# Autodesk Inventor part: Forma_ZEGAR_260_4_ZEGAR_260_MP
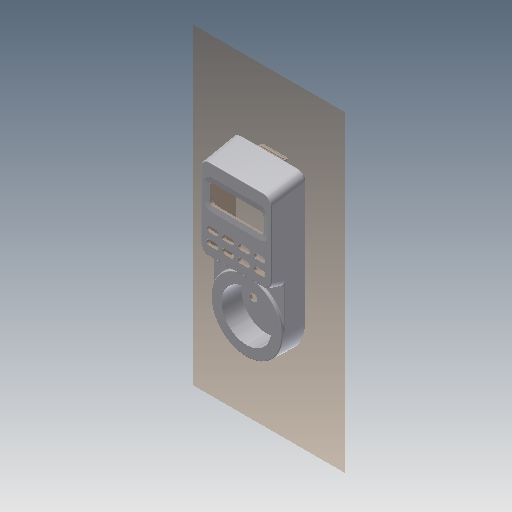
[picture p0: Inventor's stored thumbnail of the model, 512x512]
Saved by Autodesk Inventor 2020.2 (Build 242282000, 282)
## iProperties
Created: 2015-01
Part Number: Forma_ZEGAR_260_4_ZEGAR_260_MP
Material: Ogólny
Document SubType Name: Modeling
Designer: F.Stasiak
Density: 1 g/cm^3
Appearance: Domyślna
Catalog Web Link: www.expertbooks.pl
Manager: www.cadconsulting.pl
Company: Fabian Stasiak CAD Consulting
Author: F.Stasiak
Subject: Zbiór ćwiczeń. Autodesk Inventor 2020. Kurs Professional
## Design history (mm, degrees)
derived "ZEGAR_260.ipt"
node "Forma_ZEGAR_260_4_ZEGAR_260_WP"
feature "Zamknij obwiednię1" dims "d7" = 5, "d8" = 5, "d9" = 5, "d10" = 5, "d11" = 0
feature "Zamknij obwiednię2" dims "d12" = 5, "d13" = 5, "d14" = 5, "d15" = 5, "d16" = 0
feature "Zamknij obwiednię3" dims "d17" = 5, "d18" = 5, "d19" = 5, "d20" = 5, "d21" = 5, "d22" = 5, "d23" = 5, "d24" = 5, "d25" = 0
feature "Zamknij obwiednię4" dims "d26" = 5, "d27" = 5, "d28" = 5, "d29" = 5, "d30" = 0
feature "Zamknij obwiednię5" dims "d31" = 5, "d32" = 5, "d33" = 5, "d34" = 5, "d35" = 0
feature "Zamknij obwiednię6" dims "d36" = 5, "d37" = 5, "d38" = 5, "d39" = 5, "d40" = 0
feature "Zamknij obwiednię7" dims "d41" = 5, "d42" = 5, "d43" = 5, "d44" = 5, "d45" = 0
feature "Zamknij obwiednię8" dims "d46" = 5, "d47" = 5, "d48" = 5, "d49" = 5, "d50" = 0
feature "Zamknij obwiednię9" dims "d51" = 5, "d52" = 5, "d53" = 5, "d54" = 5, "d55" = 0
feature "Zamknij obwiednię10" dims "d56" = 5, "d57" = 0
feature "Zamknij obwiednię11" dims "d58" = 5, "d59" = 0
feature "Zamknij obwiednię12" dims "d60" = 5, "d61" = 0
node "Płaszczyzna konstrukcyjna1"
sketch "Szkic1"
  geometry: L1 (30.835, -178.031)-(30.835, 61.969); L2 (30.835, 61.969)-(-86.165, 61.969); L3 (-86.165, 61.969)-(-86.165, -178.031); L4 (-86.165, -178.031)-(30.835, -178.031); L5 (0, 0)-(0, -94.499) reference; L6 (-55.33, -94.499)-(-55.33, 0) reference; L7 (-49.319, 6.101)-(-6.011, 6.101) reference; A1 r 27.665 centre (-27.665, -94.499) between (-55.33, -94.499) and (0, -94.499) reference; 3 further points; 2 other entities
  constraints: 8 end point, 2 other
  dimensions: "d62" = 58.5 horizontal distance of point (-27.665, -58.031) L1.end (= 1.5 x Xmax); "d63" = 120 vertical distance of point (-27.665, -58.031) L1.end (= 1.5 x Ymax); "d64" = 58.5 horizontal distance of point (-27.665, -58.031) L2.end (= -1.5 x Xmin); "d65" = 120 vertical distance of point (-27.665, -58.031) L2.end (= 1.5 x Ymax); "d66" = 58.5 horizontal distance of point (-27.665, -58.031) L3.end (= -1.5 x Xmin); "d67" = 120 vertical distance of point (-27.665, -58.031) L3.end (= -1.5 x Ymin); "d68" = 58.5 horizontal distance of point (-27.665, -58.031) L1.start (= 1.5 x Xmax); "d69" = 120 vertical distance of point (-27.665, -58.031) L1.start (= -1.5 x Ymin)
feature "Zamknij obwiednię13" sketch "Szkic1"
feature "Oddzielenie matrycy1"
node "Płaszczyzna konstrukcyjna2"
sketch "Szkic2"
  geometry: L1 (0, -78)-(-20.191, -78) reference; L2 (-20.191, -78)-(-20.191, 0) reference; L3 (-17.791, -39)-(-12.991, -39); L4 (-17.791, -39)-(-15.391, -39); L5 (-17.791, -39)-(-17.791, -29.75); L6 (-20.191, -48.25)-(-15.391, -48.25); L7 (-15.391, -48.25)-(-15.391, -29.75); L8 (-15.391, -29.75)-(-20.191, -29.75); L9 (-20.191, -29.75)-(-20.191, -48.25)
  constraints: 14 end point, 1 horizontal, 1 perpendicular, 2 other
  dimensions: "d71" = 39 distance from line of L1 L3.start; "d72" = 2.4 distance from line of L2 L3.start; "d73" = 0 distance between parallel lines of L3 L4; "d74" = 4.8 distance between parallel lines of L9 L7; "d75" = 18.5 distance between parallel lines of L8 L6
extrude "Wyciągnięcie proste1" new body sketch "Szkic2" stored distance "d76" = 0.13; taper "d77" = 0 deg
node "Płaszczyzna konstrukcyjna3"
sketch "Szkic3"
  geometry: L1 (0, -18.5)-(-4.8, -18.5) reference; L2 (-4.8, -18.5)-(-4.8, 0) reference; L3 (-1.8, -9.25)-(4.2, -9.25); L4 (-1.8, -9.25)-(1.2, -9.25); L5 (-1.8, -9.25)-(-1.8, 5.75); L6 (-4.8, -24.25)-(1.2, -24.25); L7 (1.2, -24.25)-(1.2, 5.75); L8 (1.2, 5.75)-(-4.8, 5.75); L9 (-4.8, 5.75)-(-4.8, -24.25)
  constraints: 14 end point, 1 horizontal, 1 perpendicular, 2 other
  dimensions: "d79" = 9.25 distance from line of L1 L3.start; "d80" = 3 distance from line of L2 L3.start; "d81" = 0 distance between parallel lines of L3 L4; "d82" = 6 distance between parallel lines of L9 L7; "d83" = 30 distance between parallel lines of L8 L6
extrude "Wyciągnięcie proste2" join sketch "Szkic3" distance "d84" = 8; taper "d85" = 0 deg
feature "Bryła1::ZEGAR_260.ipt"
tag "Bryła wyprowadzona1"
feature "Bryła1::Forma_ZEGAR_260_4_ZEGAR_260_WP"
tag "Bryła wyprowadzona2"
body "Srf1"
body "Srf2"
body "Srf3"
body "Srf4"
body "Srf5"
body "Srf6"
body "Srf7"
body "Srf8"
body "Srf9"
body "Srf10"
body "Srf11"
body "Srf12"
body "Srf13"
node "Bryła3"
node "Bryła4"
node "Bryła5"
node "Bryła1"
feature "ZEGAR_260.ipt_Bodies"
node "Bryła2"
feature "Forma_ZEGAR_260_4_ZEGAR_260_WP_Bodies"
other parameters: "d1" = 39, "d2" = 39, "d6" = 0, "Xmin" = -39, "Xmax" = 39, "d70" = 0, "d78" = 0
